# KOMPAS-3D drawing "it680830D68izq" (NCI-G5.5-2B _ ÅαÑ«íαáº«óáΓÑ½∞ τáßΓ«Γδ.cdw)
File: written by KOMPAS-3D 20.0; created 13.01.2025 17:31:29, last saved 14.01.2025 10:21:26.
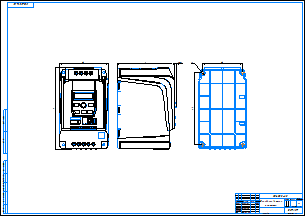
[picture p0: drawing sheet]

Sheet 1: A1, landscape

Document properties: Автор: admin; Полное имя файла: C:\Уралов Работа\Уралов (локальная)\ПЧ\! Китай 3Д-модель NCI\NCI 11-15 4B\NCI 11-15 4B.m3d

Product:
- Part/product: it680830D68izq

Title block, sheet 1: Наименование: Преобразователь / частоты; designation: NCI-G5.5-2B; Количество листов документа: 1; organisation: INSTART; cell 10: Согласовано; Форматы листов документа: A1; stored path: P:\INSTART\Технический отдел\ОР\Прочие задачи\КД на номенклатурный ряд\КД на типоразмеры ПЧ\NCI\NCI-...-4B\NCI-G11_P15-4B\NCI-G11_P15-4B _ Преобразователь частоты.cdw; Разработал: Уралов Д.А.; Проверил: Андреев Н.В.; Подписал: Смелков Ж.Е.; Утвердил: Ефремов И.Н.; Разработал, date: 13.01.25

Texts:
  Поверхности
  it680830D68izq
  it680830D68izq it680830D68izq
Dimensions and other numbers on the sheet: 1:1; 1; 13.01.25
